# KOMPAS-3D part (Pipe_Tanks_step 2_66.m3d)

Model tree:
1. X Axis
2. Y Axis
3. Z Axis  (labels: Pipe Dn 50; Valve Dy 50)
     Òîëùèíà ñòåíêè 1 = 1

Referenced files in C:\Documents and Settings\kashirsky\Мои документы\Camtasia Studio\Pipelines3D\Tanks\: Tanks_step 2.a3d
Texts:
  Pipe Dn 50
  Steel ASTM A295
  Three Point Plane
  Plane at Angle
  Line and Point Plane
  Axis through Two Vertices
  Axis of Feature
  Axis of Conical Surface
  Axis through Edge
  Trim by Surface
  Trim by Sketch
  Feature with No History
  Intersection Axis of Two Planes
  Two Line Plane
  Line and Face Plane
  Bend by line
  Hole in sheet body
  Cut in sheet body
  Point in CM
  Linear Dimension from Line to Point
  Surface Finish Symbol
  Geometric Tolerance Symbol
  Leader #1
  Leader #2
  Leader #3
  Shape Deviations and Datum
  Node point number
  Mark of coordination axis
  Node point designation
  Mark/Reference designation with leader
  Mark/reference designation on line
  Mark/Reference designation without leader
  Valve Dy 50
  Plane of section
